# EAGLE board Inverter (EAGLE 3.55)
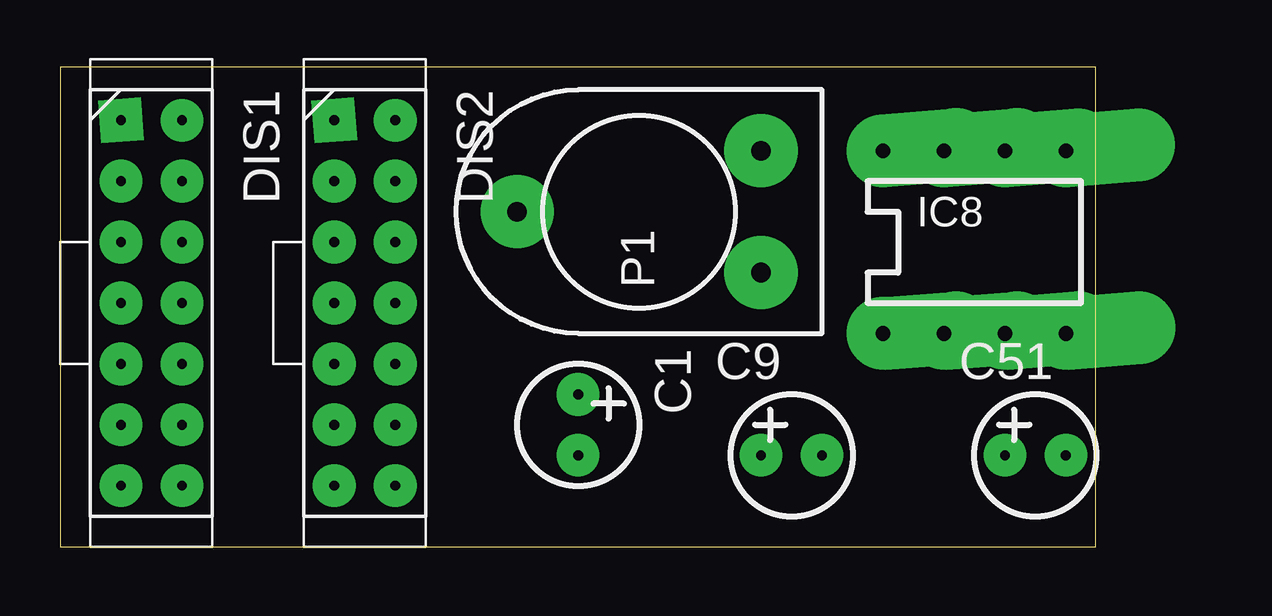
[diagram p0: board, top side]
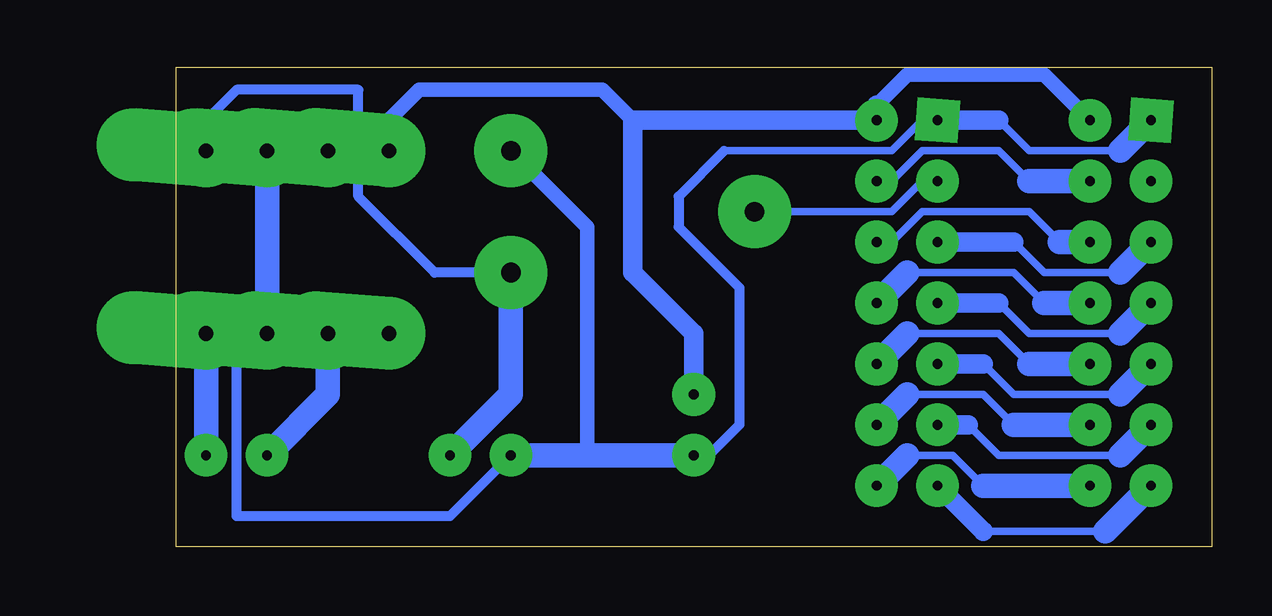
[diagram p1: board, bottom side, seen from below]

Size 43.16 x 19.99 mm. Coordinates in mm from the lower left corner, seen from the top.
Outline: 0,0 43.16,0 43.16,19.99 0,19.99 0,0
Copper layers used: Bottom

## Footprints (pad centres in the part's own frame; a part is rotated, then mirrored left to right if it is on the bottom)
KO01 = drill 0.406 pad 1.778 round:  0,0;  2.54,0
7 = drill 0.406 pad 1.778 square:  0,0 | drill 0.406 pad 1.778 round:  2.54,0;  5.08,0;  7.62,0;  10.16,0;  10.16,2.54;  7.62,2.54;  5.08,2.54;  2.54,2.54;  0,2.54;  12.7,0;  12.7,2.54;  15.24,0;  15.24,2.54
L-8B = drill 0.61 pad 3.048 offset:  0,0;  2.54,0;  5.08,0;  7.62,0;  7.62,7.62;  5.08,7.62;  2.54,7.62;  0,7.62
IM_FLA = drill 0.813 pad 3.048 round:  10.16,-2.54;  10.16,2.54;  0,0

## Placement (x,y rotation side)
C1  10u  [KO01]  21.59,6.35 270 top
C9  10u  [KO01]  29.21,3.81 0 top
C51  10u  [KO01]  39.37,3.81 0 top
DIS1  LCD In  [7]  2.54,17.78 270 top
DIS2  LCD Out  [7]  11.43,17.78 270 top
IC8  ICL7660  [L-8B]  34.29,8.89 0 top
P1  47k  [IM_FLA]  19.05,13.97 0 top

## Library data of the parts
C1 C9 C51 DIS1 DIS2 IC8 P1 = holg_plt

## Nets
+5V: C1. DIS1. DIS2. IC8.
-5V: C9. IC8. P1.
GND: C1. C9. DIS1. DIS2. IC8. P1.
N$1: DIS1. DIS2.
N$2: DIS1. DIS2.
N$3: DIS1. DIS2.
N$4: DIS1. DIS2.
N$5: DIS1. DIS2.
N$6: DIS1. DIS2.
N$7: DIS1. DIS2.
N$8: DIS1. DIS2.
N$9: DIS1. DIS2.
N$10: DIS2. P1.
N$11: DIS1. DIS2.
N$13: DIS1. DIS2.
N$83: C51. IC8.
N$84: C51. IC8.

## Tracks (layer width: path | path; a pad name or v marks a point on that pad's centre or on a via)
+5V
  Bottom 0.61: 13.97,18.41 12.7,19.68 6.99,19.68 5.08,17.78 | 24.13,17.78 25.4,19.05 33.02,19.05 34.29,17.78 IC8.
  Bottom 0.813: 21.59,6.35 21.59,8.89 24.13,11.43 24.13,17.78 13.97,17.78 13.97,18.41
-5V
  Bottom 0.406: 29.21,11.43 32.38,11.43 35.56,14.61 35.56,19.05 40.64,19.05 41.91,17.78 41.91,16.51
  Bottom 1.016: 29.21,11.43 29.21,6.35 C9.
GND
  Bottom 0.305: 3.81,16.51 7.62,16.51 8.89,17.78 | 20.32,16.51 13.34,16.51 12.06,17.78 11.43,17.78
  Bottom 0.406: 29.21,3.81 31.75,1.27 40.64,1.27 40.64,7.62 39.37,8.89 | C1. 20.95,3.81 19.68,5.08 19.68,10.79 22.23,13.34 22.23,14.61 20.32,16.51
  Bottom 0.61: 29.21,16.51 26.04,13.34 26.04,3.81
  Bottom 0.813: 8.89,17.78 11.43,17.78
  Bottom 1.016: C1. 26.04,3.81 29.21,3.81 | 3.81,16.51 2.54,17.78 | 39.37,8.89 39.37,16.51
N$1
  Bottom 0.305: 3.81,8.89 7.62,8.89 8.89,10.16
  Bottom 0.813: 8.89,10.16 11.43,10.16
  Bottom 1.016: 3.81,8.89 2.54,10.16
N$2
  Bottom 0.305: 6.35,12.7 7.62,13.97 12.06,13.97 13.34,12.7 13.97,12.7
  Bottom 1.016: 5.08,12.7 6.35,12.7
N$3
  Bottom 0.305: 6.99,10.16 8.26,11.43 12.7,11.43
  Bottom 1.016: 5.08,10.16 6.99,10.16 | 12.7,11.43 13.97,10.16
N$4
  Bottom 0.305: 3.81,6.35 8.26,6.35 9.53,7.62
  Bottom 0.813: 9.53,7.62 11.43,7.62
  Bottom 1.016: 3.81,6.35 2.54,7.62
N$5
  Bottom 0.305: 7.62,7.62 8.89,8.89 12.7,8.89
  Bottom 1.016: 5.08,7.62 7.62,7.62 | 12.7,8.89 13.97,7.62
N$6
  Bottom 0.305: 3.81,3.81 8.89,3.81 10.16,5.08
  Bottom 0.813: 10.16,5.08 11.43,5.08
  Bottom 1.016: 3.81,3.81 2.54,5.08
N$7
  Bottom 0.305: 3.81,11.43 6.99,11.43 8.26,12.7
  Bottom 0.813: 8.26,12.7 11.43,12.7
  Bottom 1.016: 3.81,11.43 2.54,12.7
N$8
  Bottom 0.305: 7.62,15.24 8.89,16.51 12.06,16.51 13.34,15.24 13.97,15.24
  Bottom 1.016: 5.08,15.24 7.62,15.24
N$9
  Bottom 0.305: 8.26,5.08 9.53,6.35 12.7,6.35
  Bottom 1.016: 5.08,5.08 8.26,5.08 | 12.7,6.35 13.97,5.08
N$10
  Bottom 0.305: 11.43,15.24 12.06,15.24 13.34,13.97 P1.
N$11
  Bottom 0.305: 4.45,0.64 9.53,0.64
  Bottom 0.813: 9.53,0.64 11.43,2.54
  Bottom 1.016: 4.45,0.64 2.54,2.54
N$13
  Bottom 0.305: 9.53,2.54 10.79,3.81 12.7,3.81
  Bottom 1.016: DIS1. 9.53,2.54 | 12.7,3.81 DIS2.
N$83
  Bottom 1.016: 36.83,8.89 36.83,6.35 39.37,3.81
N$84
  Bottom 1.016: C51. 41.91,8.89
